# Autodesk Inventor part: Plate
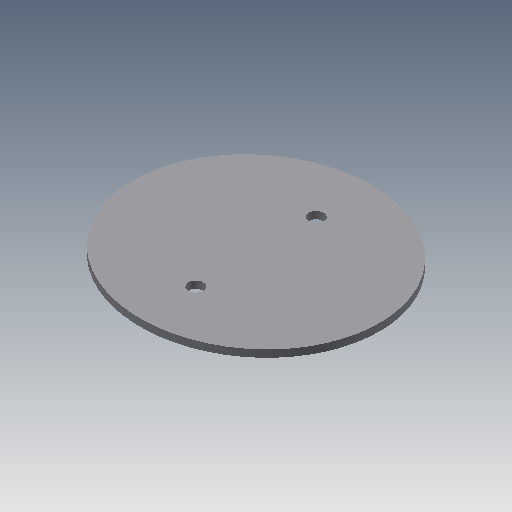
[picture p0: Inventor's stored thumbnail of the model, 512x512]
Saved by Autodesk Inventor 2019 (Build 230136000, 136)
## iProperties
Created: 2009-04
Part Number: Plate
Document SubType Name: Modeling
Designer: Sham
Density: 1 g/cm^3
Material: Generic
Appearance: Default
Author: Sham
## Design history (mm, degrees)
sketch "Sketch1"
  geometry: C1 r 6.25 at (-50, 0); C2 r 6.25 at (50, 0); 4 further points; 1 other entity
  constraints: 2 centre point, 1 coincident, 5 other
  dimensions: "d1" = 12.5 diameter of C1; "d2" = 12.5 diameter of C2; "d3" = 100 distance of C2.centre C1.centre; "d4" = 102.5 distance of point (0, 0) point (0, 102.5); "d5" = 96 distance of point (0, 0) point (-96, 0); "d6" = 50 distance of point (0, 0) C1.centre
extrude "Extrusion1" new body sketch "Sketch1" distance "d7" = 6; taper "d8" = 0 deg
body "Solid1"
